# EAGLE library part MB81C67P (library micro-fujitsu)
MICROCONTROLLER/MEMORY DEVICE
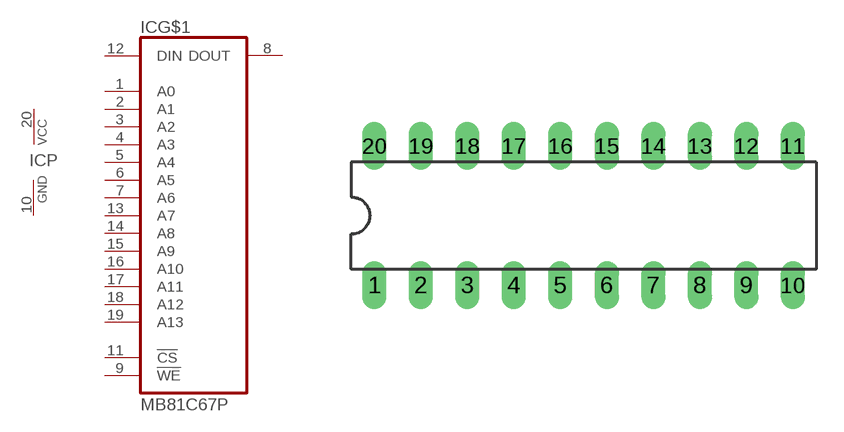
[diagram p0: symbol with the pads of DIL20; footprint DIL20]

Designator prefix IC; gates G$1=MB81C67 P=VCC-GND

## MB81C67P (OC_FARNELL: unknown; OC_NEWARK: unknown)  [DIL20]
1  G$1:A0  in
2  G$1:A1  in
3  G$1:A2  in
4  G$1:A3  in
5  G$1:A4  in
6  G$1:A5  in
7  G$1:A6  in
8  G$1:DOUT  out
9  G$1:!WE  in
10  P:GND  pwr
11  G$1:!CS  in
12  G$1:DIN  in
13  G$1:A7  in
14  G$1:A8  in
15  G$1:A9  in
16  G$1:A10  in
17  G$1:A11  in
18  G$1:A12  in
19  G$1:A13  in
20  P:VCC  pwr

## Footprint DIL20 (pad centres in mm)
Dual In Line Package
drill 0.813 long: 1 -11.43,-3.81; 2 -8.89,-3.81; 3 -6.35,-3.81; 4 -3.81,-3.81; 5 -1.27,-3.81; 6 1.27,-3.81; 7 3.81,-3.81; 8 6.35,-3.81; 9 8.89,-3.81; 10 11.43,-3.81; 11 11.43,3.81; 12 8.89,3.81; 13 6.35,3.81; 14 3.81,3.81; 15 1.27,3.81; 16 -1.27,3.81; 17 -3.81,3.81; 18 -6.35,3.81; 19 -8.89,3.81; 20 -11.43,3.81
